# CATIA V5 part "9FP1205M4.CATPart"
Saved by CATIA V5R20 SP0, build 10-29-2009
Part number: 9FP1205M4
Revision: ANY
Definition: UNKNOWN
Nomenclature: 9FP1205M4
Source: Unknown
Bounding box of the stored display mesh (mm): x -5.752 to 5.752, y 0 to 5, z -5.9 to 5.9
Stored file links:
  C:\Users\Utente\Desktop\IO LAVORO\3D X SITO CF\CUMSA\3D files PW\pw060822\pw060822_ejection\9FP1205M4.CATPart
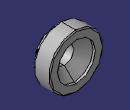
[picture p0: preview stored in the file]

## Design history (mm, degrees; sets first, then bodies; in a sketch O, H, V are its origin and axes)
Body1 "Redondeo2" (main body)
  Solid1: solid without history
